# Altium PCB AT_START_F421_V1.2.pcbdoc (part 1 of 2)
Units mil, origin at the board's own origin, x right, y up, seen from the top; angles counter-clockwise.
Board outline 4706.37 x 3915.64 mil, 2 copper layers (Top Layer, Bottom Layer); 115 components, 101 nets, 469 pads, 319 vias.
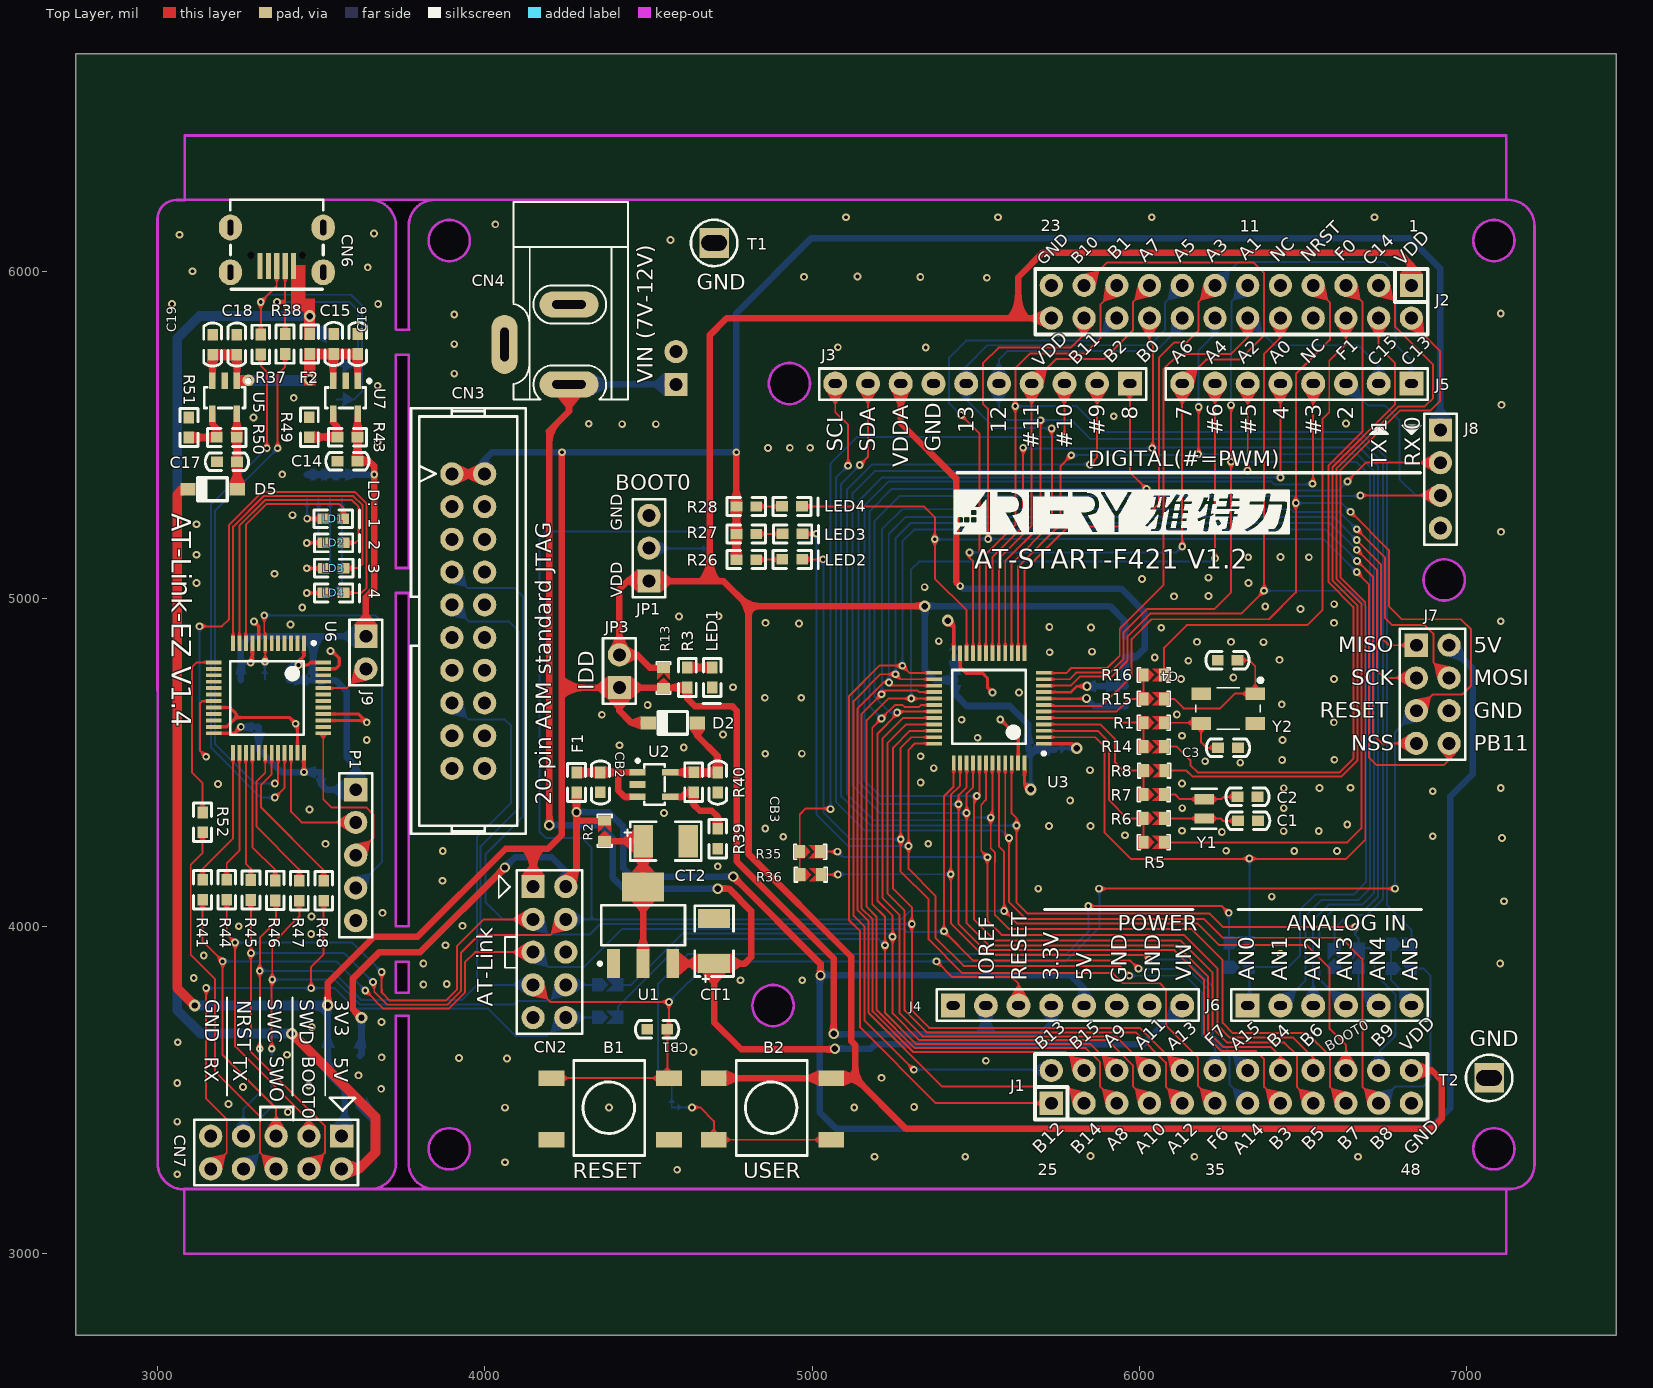
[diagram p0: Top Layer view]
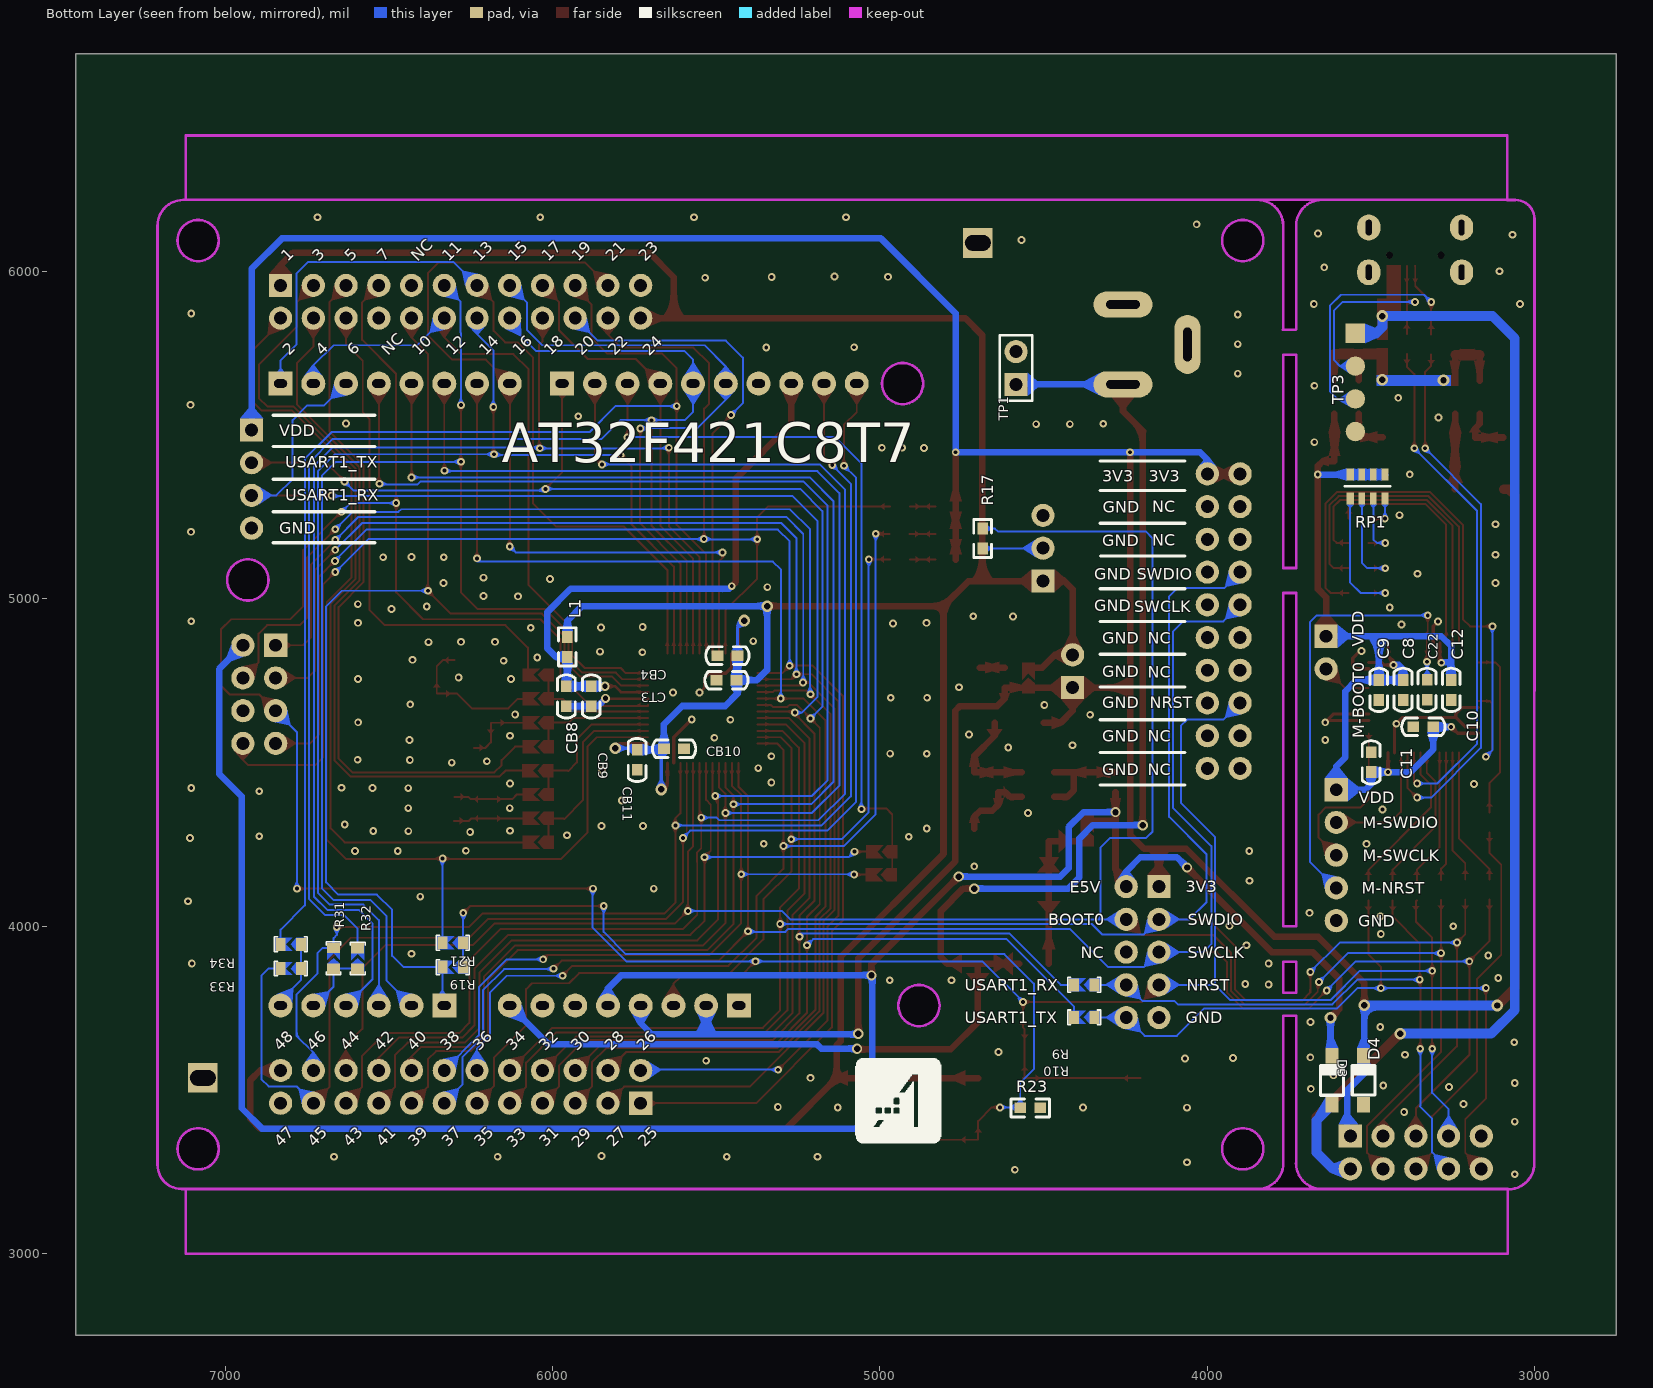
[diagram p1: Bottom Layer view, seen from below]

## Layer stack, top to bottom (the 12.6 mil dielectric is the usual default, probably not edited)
Top Layer: signal copper (thickness not stored)
Dielectric: dielectric 12.6, FR-4, Dk 4.8
Bottom Layer: signal copper (thickness not stored)

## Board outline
7456.37,2750 2750,2750 2750,6665.64 7456.37,6665.64
cut-out: 3727.81,3891.14 3766.62,3891.14 3767.37,3890.39 3767.37,3798.39 3766.52,3797.54 3727.68,3797.54
cut-out: 3728.37,4001.39 3767.37,4001.39 3767.37,5017.39 3728.37,5017.39
cut-out: 3767.37,5095.39 3767.37,5745.39 3728.37,5745.39 3728.37,5095.39
cut-out: 3728.37,3725.33 3767.37,3725.33 3767.37,3275.59 ccw(c3845.39,3275.59) 3845.39,3197.57 3649.76,3197.57 3649.76,3197.67 3650.4,3197.67 ccw(c3650.4,3275.65) 3728.37,3275.65
cut-out: 3767.63,5823.39 3728.11,5823.39 3728.11,6140.05 ccw(c3649.37,6140.05) 3649.37,6218.79 3846.15,6218.79 ccw(c3846.37,6140.05) 3767.63,6140.05
cut-out: 3846.15,6218.79 3846.37,6218.79 ccw(c3846.37,6140.05)
cut-out: 6931.05,5121.15 ccw(c6931.75,5056.84) 6867.44,5056.84 ccw(c6928.36,5056.73) 6927.55,4995.82 ccw(c6929.3,5058.48) 6931.05,5121.15
cut-out: 4931.05,5721.15 ccw(c4931.75,5656.84) 4867.44,5656.84 ccw(c4928.36,5656.73) 4927.55,5595.82 ccw(c4929.3,5658.48) 4931.05,5721.15
cut-out: 4881.05,3821.15 ccw(c4881.75,3756.84) 4817.44,3756.84 ccw(c4878.36,3756.73) 4877.55,3695.82 ccw(c4879.3,3758.49) 4881.05,3821.15
cut-out: 3892.05,3383.31 ccw(c3892.75,3319.01) 3828.44,3319 ccw(c3889.36,3318.9) 3888.55,3257.99 ccw(c3890.3,3320.65) 3892.05,3383.31
cut-out: 3892.07,6158 ccw(c3892.77,6093.69) 3828.46,6093.69 ccw(c3889.37,6093.58) 3888.57,6032.67 ccw(c3890.31,6095.34) 3892.07,6158
cut-out: 7083.05,6158 ccw(c7083.75,6093.69) 7019.44,6093.69 ccw(c7080.36,6093.58) 7079.55,6032.67 ccw(c7081.3,6095.34) 7083.05,6158
cut-out: 7083.05,3383.31 ccw(c7083.75,3319.01) 7019.44,3319 ccw(c7080.36,3318.9) 7079.55,3257.99 ccw(c7081.3,3320.65) 7083.05,3383.31

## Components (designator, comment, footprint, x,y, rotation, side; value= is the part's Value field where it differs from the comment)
B1 "PB,BLACK,SMD_2P" KEY_SOP_6*6 4203.37,3535.9 r0 top
B2 "PB,Blue,SMD_2P" KEY_SOP_6*6 4699.37,3535.9 r0 top
C1 "10pF" C0603 6300.61,4322.3 r0 top
C2 "10pF" C0603 6298.81,4395.51 r0 top
C3 "22pF" C0603 6239.42,4545.01 r0 top
C4 "22pF" C0603 6299.46,4813.05 r180 top
C8 "4.7uF" C0603 3401.34,4691.19 r90 bottom
C9 "0.1uF" C0603 3475.34,4691.19 r90 bottom
C10 "0.1uF" C0603 3370.45,4609.04 r180 bottom
C11 "0.1uF" C0603 3499.33,4531.85 r270 bottom
C12 "0.1uF" C0603 3254.34,4691.19 r90 bottom
C14 "10uF" C0603 3611.13,5421.07 r180 top
C15 "10uF" C0603 3538.55,5748.04 r90 top
C16 "0.1uF" C0603 3611.75,5748.08 r90 top
C17 "10uF" C0603 3243.13,5419.15 r180 top
C18 "10uF" C0603 3242.55,5746.04 r90 top
C19 "0.1uF" C0603 3168.55,5746.04 r90 top
C22 "0.1uF" C0603 3328.55,4753.15 r270 bottom
CB1 "0.1uF" C0603 4557.29,3685.29 r180 top
CB2 "1uF" C0603 4352.99,4470.15 r270 top
CB3 "1uF" C0603 4711.17,4469.85 r270 top
CB4 "0.1uF" C0603 5434.41,4827.14 r0 bottom
CB8 "1uF" C0603 5957.46,4733.24 r270 bottom
CB9 "0.1uF" C0603 5881.8,4733.24 r270 bottom
CB10 "0.1uF" C0603 5659.33,4541.73 r180 bottom
CB11 "0.1uF" C0603 5741.58,4538.9 r270 bottom
CN2 "CON10" HDR2X5 4147.19,4121.2 r270 top
CN3 "J-TAG" JTAG_20 3949.37,4932.09 r270 top
CN4 "DC_JACK" DC10B 4087.08,6074.51 r270 top
CN6 "USB_micro B" USB_MIC_DIP 3364.47,6017.38 r90 top
CN7 "CON10" HDR2X5 3562.55,3359.15 r180 top
CT1 "10uF/25V" C3528 4700.37,3886.09 r90 top
CT2 "10uF/25V" C3528 4483.37,4260.09 r0 top
CT3 "4.7uF" C0603 5437.41,4752.14 r0 bottom
D2 "DFLS130L" SOD-123 4573.92,4621.29 r0 top
D3 "DFLS130L" SOD-123 3618.54,3529.2 r270 bottom
D4 "SMF3.3A" SOD-123 3522.07,3529.86 r270 bottom
D5 "DFLS130L" SOD-123 3168.13,5335.15 r0 top
F1 "SMD0603B025TF" r0603 4280.19,4408.93 r90 top
F2 "SMD0603B025TF" r0603 3464.55,5809.04 r270 top
J1 "Header 12X2" HEAD2*12 5730.37,3459.51 r0 top
J2 "Header 12X2" HEAD2*12 6830.37,5957.66 r180 top
J3 "CON10" "HDR1X10 - 2#" 5970.37,5657.94 r180 top
J4 "CON8" "HDR1X8 - 2#" 5430.37,3757.94 r0 top
J5 "CON8" "HDR1X8 - 2#" 6830.37,5657.94 r180 top
J6 "CON6" "HDR1X6 -2#" 6330.37,3757.94 r0 top
J7 "Header 4X2" HDR2X4 6845.37,4858.51 r270 top
J8 "Header 4" HDR1X4 6918.97,5516.09 r270 top
J9 "1X2P_2.54M" HDR1X2 3636.55,4886.15 r270 top
JP1 "1X3P_2.54M" HDR1X3 4501.37,5055.09 r90 top
JP3 "1X2P_2.54M" HDR1X2 4410.97,4729.24 r90 top
L1 "BEAD" r0603 5954.58,4883.9 r270 bottom
LD1 "RED" LED0603 3506.59,5244.94 r0 top
LD2 "GREEN" LED0603 3507.55,5170.85 r0 top
LD3 "BLUE" LED0603 3507.59,5093.94 r0 top
LD4 "YELLOW" LED0603 3507.55,5017.94 r0 top
LED1 "RED" LED0603 4694.18,4790.28 r270 top
LED2 "RED" LED0603 4908.46,5120.29 r0 top
LED3 "YELLOW" LED0603 4909.61,5198.29 r0 top
LED4 "GREEN" LED0603 4907.61,5282.29 r0 top
P1 "Header 5" HDR1X5 3605.55,4417.15 r270 top
R1 "0R" SB-PAD 6043.39,4621.71 r0 top
R2 "0R" SB-PAD 4365.8,4291.56 r90 top
R3 "1K" r0603 4618.97,4729.31 r90 top
R5 "NC" SB-PAD 6043.43,4256.51 r0 top
R6 "0R" SB-PAD 6043.43,4329.51 r0 top
R7 "0R" SB-PAD 6043.43,4402.51 r0 top
R8 "NC" SB-PAD 6044.43,4475.58 r0 top
R9 "0R" SB-PAD 4375.64,3821.2 r0 bottom
R10 "0R" SB-PAD 4375.64,3721.65 r0 bottom
R13 "0R" SB-PAD 4545.77,4758.51 r90 top
R14 "NC" SB-PAD 6043.39,4548.71 r0 top
R15 "0R" SB-PAD 6043.39,4694.71 r0 top
R16 "NC" SB-PAD 6043.39,4767.71 r0 top
R17 "10K" r0603 4685.68,5154.09 r90 bottom
R19 "0R" SB-PAD 6304.41,3875.14 r0 bottom
R21 "NC" SB-PAD 6304.37,3949.94 r0 bottom
R23 "100K" r0603 4509.97,3445.29 r0 bottom
R26 "1K" r0603 4768.37,5120.09 r0 top
R27 "1K" r0603 4768.37,5198.09 r0 top
R28 "1K" r0603 4768.37,5282.09 r0 top
R31 "NC" SB-PAD 6668.58,3902.09 r90 bottom
R32 "0R" SB-PAD 6594.87,3901.66 r90 bottom
R33 "NC" SB-PAD 6798.97,3871 r0 bottom
R34 "0R" SB-PAD 6798.97,3945 r0 bottom
R35 "NC" SB-PAD 4993.37,4227.94 r0 top
R36 "0R" SB-PAD 4995.37,4157.94 r0 top
R37 "22R" r0603 3315.34,5808 r270 top
R38 "22R" r0603 3389.34,5808.96 r270 top
R39 "15K" r0603 4711.58,4237.13 r90 top
R40 "51K" r0603 4637.79,4409.45 r90 top
R41 "33R" r0603 3137.75,4081.19 r90 top
R43 "47K" r0603 3550.17,5493.87 r0 top
R44 "33R" r0603 3211.75,4081.19 r90 top
R45 "33R" r0603 3285.75,4080.19 r90 top
R46 "33R" r0603 3359.75,4079.19 r90 top
R47 "33R" r0603 3433.75,4078.19 r90 top
R48 "33R" r0603 3507.75,4078.19 r90 top
R49 "15K" r0603 3463.92,5555.03 r270 top
R50 "51K" r0603 3181.17,5492.94 r0 top
R51 "15K" r0603 3095.92,5554.11 r270 top
R52 "33R" r0603 3137.75,4286.98 r90 top
RP1 "1KΩ" RP_4-0603 3562.93,5307.03 r90 bottom
T1 "Test point" TestPoint 4700.37,6087.41 r0 top
T2 "Test point" TestPoint 7067.77,3536.94 r0 top
TP1 "1X2P_2.54M" HDR1X2 4583.83,5655.42 r90 bottom
TP3 "1X4P_2.54F" "HDR1X4 - top" 3547.13,5811.15 r270 bottom
U1 "AMS1117-5.0" SOT223 4483.37,4003.09 r90 top
U2 "RT9080N-08GJ5" SOT-23-5 4531.4,4370.15 r0 top
U3 "AT32F421C8T7" LQFP48 5540.46,4666.06 r90 top
U5 "RT9080N-08GJ5" SOT-23-5 3142.34,5601.04 r270 top
U6 "AT32F403ACCT7" "LQFP48 - 2" 3447.29,4865.15 r270 top
U7 "RT9080N-08GJ5" SOT-23-5 3511.55,5600.96 r270 top
Y1 "32.768KHz" "XTAL_SOP - FC-12M" 6197.85,4388.3 r270 top
Y2 "8MHZ" SMD_5032_4P 6270.61,4665.17 r180 top

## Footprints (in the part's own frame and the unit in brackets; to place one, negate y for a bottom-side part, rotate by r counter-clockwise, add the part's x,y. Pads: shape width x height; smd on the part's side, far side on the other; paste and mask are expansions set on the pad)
C0603 [mil]
  rect 36x32 smd mask+2: 1(-0.04,0.2) 2(60.96,0.2)
  silkscreen extent -35,-27 97,27
C3528 [mm]
  rect 1.5x2.5 smd mask+0.051: 1(0,0) 2(3.5,0)
  silkscreen extent -1.45,-1.5 4.5,1.5
DC10B [mil]
  oval 80x180 hole 25.59 slot 102.36 at 90 deg mask+2: 1(419.09,170) 2(175,170)
  oval 180x80 hole 25.59 slot 102.36 at 0 deg mask+2: 3(297.05,-26.85)
  silkscreen extent -138,0 465,350
HDR1X2 [mm]
  rect 1.8x1.8 hole 1 mask+0.051: 1(0,0)
  round 1.8 hole 1 mask+0.051: 2(2.54,0)
  silkscreen extent -1.27,-1.27 3.81,1.27
HDR1X3 [mm]
  rect 1.8x1.8 hole 1 mask+0.051: 1(0,0)
  round 1.8 hole 1 mask+0.051: 2(2.54,0) 3(5.08,0)
  silkscreen extent -1.27,-1.27 6.35,1.27
HDR1X4 [mm]
  rect 1.8x1.8 hole 1 mask+0.051: 1(0,0)
  round 1.8 hole 1 mask+0.051: 2(2.54,0) 3(5.08,0) 4(7.62,0)
  silkscreen extent -1.27,-1.27 8.89,1.27
"HDR1X4 - top" [mm]
  rect 1.5x1.5 smd mask+0.051: 1(0,0)
  round 1.5 smd mask+0.051: 2(2.54,0) 3(5.08,0) 4(7.62,0)
HDR1X5 [mm]
  rect 1.8x1.8 hole 1 mask+0.051: 1(0,0)
  round 1.8 hole 1 mask+0.051: 2(2.54,0) 3(5.08,0) 4(7.62,0) 5(10.16,0)
  silkscreen extent -1.27,-1.27 11.43,1.27
"HDR1X6 -2#" [mm]
  rect 1.86x1.86 hole 0.65 slot 1 at 0 deg mask+0.051: 1(0,0)
  round 1.86 hole 0.65 slot 1 at 0 deg mask+0.051: 2(2.54,0) 3(5.08,0) 4(7.62,0) 5(10.16,0) 6(12.7,0)
  silkscreen extent -1.27,-1.17 13.97,1.27
"HDR1X8 - 2#" [mm]
  rect 1.86x1.86 hole 0.65 slot 1 at 0 deg mask+0.051: 1(0,0)
  round 1.86 hole 0.65 slot 1 at 0 deg mask+0.051: 2(2.54,0) 3(5.08,0) 4(7.62,0) 5(10.16,0) 6(12.7,0) 7(15.24,0) 8(17.78,0)
  silkscreen extent -1.27,-1.17 19.05,1.27
"HDR1X10 - 2#" [mm]
  rect 1.86x1.86 hole 0.65 slot 1 at 0 deg mask+0.051: 1(0,0)
  round 1.86 hole 0.65 slot 1 at 0 deg mask+0.051: 2(2.54,0) 3(5.08,0) 4(7.62,0) 5(10.16,0) 6(12.7,0) 7(15.24,0) 8(17.78,0) 9(20.32,0) 10(22.86,0)
  silkscreen extent -1.27,-1.17 24.1,1.27
HDR2X4 [mm]
  rect 1.8x1.8 hole 1 mask+0.051: 1(0,0)
  round 1.8 hole 1 mask+0.051: 2(0,2.54) 3(2.54,0) 4(2.54,2.54) 5(5.08,0) 6(5.08,2.54) 7(7.62,0) 8(7.62,2.54)
  silkscreen extent -1.27,-1.27 8.89,3.81
HDR2X5 [mm]
  rect 1.8x1.8 hole 1 mask+0.051: 1(0,0)
  round 1.8 hole 1 mask+0.051: 2(0,2.54) 3(2.54,0) 4(2.54,2.54) 5(5.08,0) 6(5.08,2.54) 7(7.62,0) 8(7.62,2.54) 9(10.16,0) 10(10.16,2.54)
  silkscreen extent -1.27,-1.27 11.43,3.81
HEAD2*12 [mm]
  rect 1.8x1.8 hole 1 mask+0.051: 1(0,0)
  round 1.8 hole 1 mask+0.051: 2(0,2.54) 3(2.54,0) 4(2.54,2.54) 5(5.08,0) 6(5.08,2.54) 7(7.62,0) 8(7.62,2.54) 9(10.16,0) 10(10.16,2.54) 11(12.7,0) 12(12.7,2.54) 13(15.24,0) 14(15.24,2.54) 15(17.78,0) 16(17.78,2.54) 17(20.32,0) 18(20.32,2.54) 19(22.86,0) 20(22.86,2.54) 21(25.4,0) 22(25.4,2.54) 23(27.94,0) 24(27.94,2.54)
  silkscreen extent -1.27,-1.27 29.19,3.81
JTAG_20 [mm]
  round 1.8 hole 1 mask+0.051: 1(-11.43,-1.27) 2(-11.43,1.27) 3(-8.89,-1.27) 4(-8.89,1.27) 5(-6.35,-1.27) 6(-6.35,1.27) 7(-3.81,-1.27) 8(-3.81,1.27) 9(-1.27,-1.27) 10(-1.27,1.27) 11(1.27,-1.27) 12(1.27,1.27) 13(3.81,-1.27) 14(3.81,1.27) 15(6.35,-1.27) 16(6.35,1.27) 17(8.89,-1.27) 18(8.89,1.27) 19(11.43,-1.27) 20(11.43,1.27)
  silkscreen extent -16.51,-4.45 16.51,4.45
KEY_SOP_6*6 [mm]
  rect 2x1.2 smd mask+0.051: 1(0,0) 1(9.119,0) 2(0,-4.775) 2(9.119,-4.775)
  silkscreen extent 1.73,-5.99 7.24,1.4
LED0603 [mil]
  rect 36x32 smd mask+2: 1(-0.04,0.2) 2(60.96,0.2)
  silkscreen extent -28,-28 110,27
LQFP48 [mm]
  rect 0.3x1.2 smd mask+0.051: 1(-2.75,-4.25) 2(-2.25,-4.25) 3(-1.75,-4.25) 4(-1.25,-4.25) 5(-0.75,-4.25) 6(-0.25,-4.25) 7(0.25,-4.25) 8(0.75,-4.25) 9(1.25,-4.25) 10(1.75,-4.25) 11(2.25,-4.25) 12(2.75,-4.25) 25(2.75,4.25) 26(2.25,4.25) 27(1.75,4.25) 28(1.25,4.25) 29(0.75,4.25) 30(0.25,4.25) 31(-0.25,4.25) 32(-0.75,4.25) 33(-1.25,4.25) 34(-1.75,4.25) 35(-2.25,4.25) 36(-2.75,4.25)
  rect 1.2x0.3 smd mask+0.051: 13(4.25,-2.75) 14(4.25,-2.25) 15(4.25,-1.75) 16(4.25,-1.25) 17(4.25,-0.75) 18(4.25,-0.25) 19(4.25,0.25) 20(4.25,0.75) 21(4.25,1.25) 22(4.25,1.75) 23(4.25,2.25) 24(4.25,2.75) 37(-4.25,2.75) 38(-4.25,2.25) 39(-4.25,1.75) 40(-4.25,1.25) 41(-4.25,0.75) 42(-4.25,0.25) 43(-4.25,-0.25) 44(-4.25,-0.75) 45(-4.25,-1.25) 46(-4.25,-1.75) 47(-4.25,-2.25) 48(-4.25,-2.75)
  silkscreen extent -3.64,-4.37 2.96,2.86
"LQFP48 - 2" [mm]
  rect 1.2x0.3 smd mask+0.051: 1(0,0) 2(0,-0.5) 3(0,-1) 4(0,-1.5) 5(0,-2) 6(0,-2.5) 7(0,-3) 8(0,-3.5) 9(0,-4) 10(0,-4.5) 11(0,-5) 12(0,-5.5) 25(8.5,-5.5) 26(8.5,-5) 27(8.5,-4.5) 28(8.5,-4) 29(8.5,-3.5) 30(8.5,-3) 31(8.5,-2.5) 32(8.5,-2) 33(8.5,-1.5) 34(8.5,-1) 35(8.5,-0.5) 36(8.5,0)
  rect 0.3x1.2 smd mask+0.051: 13(1.5,-7) 14(2,-7) 15(2.5,-7) 16(3,-7) 17(3.5,-7) 18(4,-7) 19(4.5,-7) 20(5,-7) 21(5.5,-7) 22(6,-7) 23(6.5,-7) 24(7,-7) 37(7,1.5) 38(6.5,1.5) 39(6,1.5) 40(5.5,1.5) 41(5,1.5) 42(4.5,1.5) 43(4,1.5) 44(3.5,1.5) 45(3,1.5) 46(2.5,1.5) 47(2,1.5) 48(1.5,1.5)
  silkscreen extent -0.12,-5.71 7.11,0.89
r0603 [mil]
  rect 36x32 smd mask+2: 1(-0.04,0.2) 2(60.96,0.2)
  silkscreen extent -28,-27 89,27
RP_4-0603 [mm]
  rect 0.95x0.55 smd mask+0.051: 1(0,-2.7) 4(0,0) 5(1.85,0) 8(1.85,-2.7)
  rect 0.95x0.5 smd mask+0.051: 2(0,-1.8) 3(0,-0.9) 6(1.85,-0.9) 7(1.85,-1.8)
  silkscreen extent 0.94,-3.1 0.94,0.43
SB-PAD [mm]
  rect 0.8x1 smd paste+0.102 mask+0.102: 1(-0.799,0.003) 2(0.799,0.002)
  Top Layer region: -1.2,-0.5 -1.2,0.5 -0.418,0.5 0.025,0 -0.433,-0.5
  Top Layer region: -0.119,0.5 0.381,0 -0.119,-0.5 1.2,-0.5 1.2,0.5
  silkscreen extent -1.28,-0.58 1.28,0.58
SMD_5032_4P [mm]
  rect 1.5x1 smd mask+0.051: 1(-2.1,-1.15) 2(2.1,-1.15) 3(2.1,1.15) 4(-2.1,1.15)
  silkscreen extent -2.65,-2.35 2.5,1.6
SOD-123 [mm]
  rect 1.2x1 smd mask+0.051: 1(1.905,0) 2(-1.905,0)
  silkscreen extent -1.14,-0.89 1.14,0.89
SOT223 [mm]
  rect 2.25x1 smd mask+0.051: 1(-2.975,2.3) 2(-2.975,0) 3(-2.975,-2.3)
  rect 2.25x3.25 smd mask+0.051: 4(2.975,0)
  silkscreen extent -3.1,-3.25 1.55,3.47
SOT-23-5 [mil]
  rect 50x20 smd mask+2: 1(-65,100) 2(-65,63) 3(-65,25) 4(35,25) 5(35,100)
  silkscreen extent -65,1 18,135
TestPoint [mm]
  rect 2.3x2.3 hole 1.2 slot 2 at 0 deg mask+0.051: 1(0,0)
  silkscreen extent -1.8,-1.8 1.8,1.8
USB_MIC_DIP [mm]
  rect 2x0.4 smd mask+0.051: 1(0,-1.3) 2(0,-0.65) 3(0,0) 4(0,0.65) 5(0,1.3)
  oval 2x1.8 hole 0.45 slot 1.2 at 0 deg mask+0.051: 6(-0.495,-3.6) 7(2.975,-3.6) 8(2.975,3.6) 9(-0.495,3.6)
  round 0.5 hole 0.55 unplated mask+0.051: MH1(0.825,2) MH2(0.825,-2)
  silkscreen extent -1.82,-3.6 5.12,3.6
"XTAL_SOP - FC-12M" [mm]
  rect 0.8x1.5 smd mask+0.051: 1(0,0) 2(1.5,0)
  silkscreen extent -0.81,-0.99 2.29,0.94

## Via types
v1: diameter 23.62, hole 11.81, Top Layer to Bottom Layer, 298 vias
v2: diameter 35.43, hole 19.68, Top Layer to Bottom Layer, 11 vias
v3: diameter 31.5, hole 19.68, Top Layer to Bottom Layer, 8 vias
v4: diameter 27.56, hole 15.75, Top Layer to Bottom Layer, 2 vias

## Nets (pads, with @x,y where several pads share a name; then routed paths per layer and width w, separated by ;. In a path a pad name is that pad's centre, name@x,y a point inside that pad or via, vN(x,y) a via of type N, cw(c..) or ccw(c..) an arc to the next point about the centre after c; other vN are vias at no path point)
3V3: CN2.1 CN3.1 CN3.2 CN7.1 D2.2 D4.2 D5.2 J4.2 J4.4 J8.1 JP3.1 R3.1 R13.1 R26.1 R27.1 R28.1 | length 11849
  Top Layer w20: v2(3520,3758.39) 3520,3826.85 3661.09,3967.94 3794.35,3967.94 4063.5,4237.09 4147.19,4237.09 ; CN3.1@3899.37,5382.09 CN3.2@3999.37,5382.09 ; CN2.1@4147.19,4121.2 4147.19,4237.09 ; v1(4235.37,5447.94) 4235.37,4729.31 ; JP3.1@4410.97,4729.24 4545.77,4729.2 R13.1@4545.97,4728.99 ; D2.2@4498.92,4621.29 4448.11,4621.29 4410.97,4658.44 JP3.1@4410.97,4729.24 4235.45,4729.24 4235.37,4729.31 ; R13.1@4545.77,4729.24 R3.1@4618.73,4729.24 ; R3.1@4618.77,4729.28 4618.77,4694.88 4641.13,4672.52 4755.36,4672.52 4769.37,4658.51 4769.37,4198.09 5065.37,3902.09 v3(5065.37,3672.09) ; R26.1@4768.33,5120.29 R27.1@4768.33,5198.29 R28.1@4768.33,5282.29 v1(4768.33,5448.13) ; 4147.19,4237.09 4192.56,4237.09 4235.37,4279.9 4235.37,4729.31
  Top Layer w30: D5.2@3093.13,5335.15 3077.28,5335.15 3060.07,5317.94 3060.07,3811.2 v2(3113.33,3757.94)
  Bottom Layer w20: v2(3520,3758.39) 3520,3606.93 D4.2@3522.07,3604.86 3522.07,3548.59 3572.65,3498.01 3572.65,3369.25 CN7.1@3562.55,3359.15 ; CN3.2@3999.37,5382.09 3999.37,5426.09 4021.41,5448.13 v1(4768.33,5448.13) 4768.33,5872.85 4996.57,6101.09 6826.37,6101.09 6918.97,6008.49 J8.1@6918.97,5516.09 ; v3(5065.37,3672.09) 5067.37,3670.09 5532.37,3670.09 ; J4.2@5530.37,3757.94 5530.37,3672.09 5532.37,3670.09 ; J4.4@5730.37,3757.94 5730.37,3704.09 5696.37,3670.09 5532.37,3670.09
  Bottom Layer w30: v2(3113.33,3757.94) v2@3519.55,3757.94
5V: CN2.2 D3.2 F1.1 J4.5 J7.2 R2.2 | length 7292.7
  Top Layer w6: 4279.99,4329.09 4286.05,4323.03
  Top Layer w20: v2(3623.16,3720.46) 3597.12,3746.51 3597.12,3840.57 3677.74,3921.2 3802.87,3921.2 v3(4061.26,4179.59) ; CN2.2@4247.19,4121.2 4247.19,4140.9 4279.99,4173.71 4279.99,4329.09 v3(4279.99,4349.02) F1.1@4279.99,4408.89 ; 4286.05,4323.03 R2.2@4365.72,4323.03 ; v3(4758.61,4151.85) 5025.37,3885.09 v3(5025.37,3849.94)
  Bottom Layer w20: D3.2@3618.54,3604.2 3623.16,3608.81 v2(3623.16,3720.46) ; v3(4061.26,4179.59) 4092.36,4210.7 4204.06,4210.7 4247.19,4167.57 CN2.2@4247.19,4121.2 ; v3(4279.99,4349.02) 4377.18,4349.02 4423.14,4303.06 4423.14,4177.32 4448.61,4151.85 v3(4758.61,4151.85) ; J4.5@5830.37,3757.94 5830.37,3809.94 5789.37,3850.94 5026.37,3850.94 v3(5025.37,3849.94) 5022.37,3846.94 5022.37,3432.09 5072.37,3382.09 6887.37,3382.09 6949.3,3444.01 6949.3,4396.67 7018.37,4465.74 7018.37,4785.51 J7.2@6945.37,4858.51
$1N792: LD1.1 RP1.1 | length 111.5
  Top Layer w6: v1(3457.07,5245.15) LD1.1@3506.55,5245.15
  Bottom Layer w6: RP1.1@3456.63,5307.03 3456.63,5245.58 v1(3457.07,5245.15)
$1N793: LD2.1 RP1.2 | length 217.4
  Top Layer w6: v1(3456.07,5171.05) LD2.1@3507.51,5171.05
  Bottom Layer w6: v1(3456.07,5171.05) 3481.74,5171.05 3492.07,5181.38 RP1.2@3492.07,5307.03
$1N794: LD3.1 RP1.3 | length 326.6
  Top Layer w6: v1(3456.07,5093.86) 3507.26,5093.86 LD3.1@3507.55,5094.15
  Bottom Layer w6: v1(3456.07,5093.86) 3511.07,5093.86 3527.5,5110.29 RP1.3@3527.5,5307.03
$1N795: LD4.1 RP1.4 | length 428.7
  Top Layer w6: v1(3456.07,5018.15) LD4.1@3507.51,5018.15
  Bottom Layer w6: v1(3456.07,5018.15) 3531.35,5018.15 3562.93,5049.73 RP1.4@3562.93,5307.03
$1N806: C15.1 C16.1 C18.1 C19.1 F2.2 U5.1 U5.3 U7.1 U7.3 | length 541.8
  Top Layer w20: U5.3@3167.34,5666.04 3167.34,5745 C19.1@3168.34,5746 ; U5.1@3242.34,5666.04 C18.1@3242.34,5746 ; U7.3@3536.55,5668.04 C15.1@3536.55,5746.2 ; U7.1@3611.55,5668.04 C16.1@3611.55,5748.04
  Top Layer w30: C19.1@3168.34,5746 C18.1@3242.34,5746 ; F2.2@3464.75,5748.08 3538.34,5748.08 C16.1@3611.51,5748.08 ; C15.1@3536.55,5746.2 C15.1@3538.34,5748
  other v2: 3278.07,5667.86 3465.55,5669.15
$1N944: R50.1 R51.2 U5.4 | length 163.6
  Top Layer w20: R51.2@3096.13,5493.15 R50.1@3181.13,5493.15 3181.13,5521.15 3167.34,5534.93 U5.4@3167.34,5566.04
$1N945: R43.1 R49.2 U7.4 | length 163.5
  Top Layer w20: R49.2@3464.13,5494.07 R43.1@3550.13,5494.07 3550.13,5525.07 3536.55,5538.65 U7.4@3536.55,5565.96
$2N438: C2.1 R7.2 Y1.1 | length 232.8
  Top Layer w6: R7.2@6074.9,4402.58 6108.93,4402.58 6123.21,4388.3 Y1.1@6197.85,4388.3 6249.85,4388.3 6257.06,4395.51 C2.1@6298.81,4395.51
$2N447: C1.1 R6.2 Y1.2 | length 228.3
  Top Layer w6: R6.2@6074.9,4329.58 6114.45,4329.58 ; 6114.78,4329.25 Y1.2@6197.85,4329.25 6247.91,4329.25 6254.85,4322.3 C1.1@6300.61,4322.3
$2N462: R7.1 R8.1 U3.4 | length 478.8
  Top Layer w6: U3.4@5707.79,4616.85 5879.21,4616.85 5925.05,4571.01 5925.05,4500.97 5951.85,4474.17 5953.37,4475.68 R8.1@6012.96,4475.68 ; R7.1@6011.96,4402.61 R8.1@6011.96,4475.51
$2N463: R1.1 R14.1 U3.5 | length 383.2
  Top Layer w6: U3.5@5707.79,4636.53 5934.73,4636.53 5949.45,4621.81 R1.1@6011.92,4621.81 R14.1@6011.92,4548.81
$2N464: R15.1 R16.1 U3.6 | length 393.1
  Top Layer w6: U3.6@5707.79,4656.22 5930.19,4656.22 5968.79,4694.81 R15.1@6011.92,4694.81 R16.1@6011.92,4767.81
$2N471: R5.1 R6.1 U3.3 | length 592.2
  Top Layer w6: U3.3@5707.79,4597.16 5871.57,4597.16 5906.68,4562.05 5906.68,4385.21 5964.27,4327.62 5966.26,4329.61 R6.1@6011.96,4329.61 ; R5.1@6011.44,4257.13 R6.1@6011.44,4329.09
$2N484: JP1.2 R17.1 | length 185.1
  Bottom Layer w6: JP1.2@4501.37,5155.09 ccw(c4502.37,5155.09) 4502.37,5154.09 R17.1@4685.88,5154.09
$2N487: C3.1 R1.2 Y2.3 | length 230.4
  Top Layer w6: R1.2@6074.86,4621.79 6186.04,4621.79 Y2.3@6187.93,4619.9 6187.93,4561.66 6204.37,4545.22 C3.1@6239.38,4545.22
$2N488: C4.1 R15.2 Y2.1 | length 454
  Top Layer w6: R15.2@6074.86,4694.79 6105.52,4694.79 6134.37,4665.94 6246.37,4665.94 6290.88,4710.45 Y2.1@6353.28,4710.45 6353.28,4794.03 6334.47,4812.85 C4.1@6299.5,4812.85
$3N526: LED1.1 R3.2 | length 75.4
  Top Layer w20: R3.2@4618.77,4790.28 LED1.1@4694.18,4790.28
$3N531: CB3.1 D2.1 R40.2 U2.5 | length 321.1
  Top Layer w6: R40.2@4637.33,4470.15 R40.2@4637.59,4470.41
  Top Layer w20: U2.5@4566.4,4470.15 R40.2@4637.33,4470.15 ; R40.2@4637.59,4470.41 4710.85,4470.41 4710.85,4520.42 4648.92,4582.35 D2.1@4648.92,4621.29
$3N595: B2.2 R19.1 R21.1 R23.2 | length 3021.5
  Top Layer w6: v1(4633.09,3446.74) 4657.58,3446.74 4699.37,3404.95 B2.2@4699.37,3347.9 B2.2@5058.37,3347.9 ; v1(5843.33,4061.94) 6251.52,4061.94 v1(6272.52,4040.94)
  Bottom Layer w6: R23.2@4570.93,3445.09 R23.2@4570.93,3446.74 ; v1(4633.09,3446.74) R23.2@4570.93,3446.74 ; v1@5843.37,4061.94 5843.37,3982.94 5775.37,3914.94 4619.24,3914.94 4529.37,3825.07 4529.37,3563.94 4570.93,3522.38 R23.2@4570.93,3446.74 ; v1(6272.52,4040.94) v1@6272.95,4040.94 ; R21.1@6272.91,3949.84 v1@6272.91,4040.9 ; R19.1@6272.95,3875.04 R21.1@6272.91,3949.84
$3N598: LED3.1 R27.2 | length 80.3
  Top Layer w6: R27.2@4829.33,5198.29 LED3.1@4909.61,5198.29
$3N599: LED4.1 R28.2 | length 78.3
  Top Layer w6: R28.2@4829.33,5282.29 LED4.1@4907.61,5282.29
$3N606: LED2.1 R26.2 | length 79.1
  Top Layer w6: R26.2@4829.33,5120.29 LED2.1@4908.46,5120.29
$3N618: R39.2 R40.1 U2.4 | length 240.7
  Top Layer w20: U2.4@4566.4,4395.15 4601.92,4395.15 4616.19,4409.41 R40.1@4637.59,4409.41 4637.59,4371.87 4656.37,4353.09 4693.37,4353.09 4711.37,4335.08 R39.2@4711.37,4298.09
$3N621: CT2.1 R2.1 U1.2 U1.4 | length 491.8
  Top Layer w20: R2.1@4365.69,4260.09 CT2.1@4483.37,4260.09 U1.4@4483.37,4120.21 U1.2@4483.37,3885.96
$3N625: CB2.1 F1.2 U2.1 U2.3 | length 306.8
  Top Layer w6: F1.2@4279.99,4469.89 F1.2@4280.29,4470.19
  Top Layer w20: F1.2@4280.29,4470.19 CB2.1@4353.19,4470.19 U2.1@4466.4,4470.15 ; 4407.4,4468.19 4407.4,4415.15 4427.4,4395.15 U2.3@4466.4,4395.15
A0: J2.10 J6.1 R19.2 U3.10 | length 3527
  Top Layer w6: U3.10@5707.79,4734.96 5789.39,4734.96 5817.37,4762.94 5914.37,4762.94 5963.37,4811.94 5963.37,4885.94 6032.37,4954.94 6310.37,4954.94 v1(6380.37,5024.94) 6380.37,5748.94 6429.95,5798.52 J2.10@6429.95,5857.24
  Bottom Layer w6: J6.1@6330.37,3757.94 6335.88,3763.45 R19.2@6335.88,3875.07 6454.7,3875.07 6489.37,3909.74 6489.37,4049.94 6536.37,4096.94 6654.37,4096.94 6691.37,4133.94 6691.37,4976.94 6643.37,5024.94 v1(6380.37,5024.94)
A1: J2.11 J6.2 U3.11 | length 3928.1
  Top Layer w6: U3.11@5707.79,4754.64 5786.08,4754.64 5806.37,4774.94 5909.16,4774.94 5951.37,4817.15 5951.37,4897.94 6022.37,4968.94 6228.37,4968.94 6279.37,5019.94 v1(6279.37,5418.94) v1(6279.37,5591.94)
  Bottom Layer w6: v1(6279.37,5418.94) 6662.37,5418.94 6704.37,5376.94 6704.37,4115.94 6669.37,4080.94 6556.37,4080.94 6507.37,4031.94 6507.37,3834.94 J6.2@6430.37,3757.94 ; v1(6279.37,5591.94) 6279.37,5812.94 6281.37,5814.94 6281.37,5908.66 J2.11@6329.95,5957.24
A2: J2.14 J6.3 U3.14 | length 3826.2
  Top Layer w6: U3.14@5629.05,4833.38 5629.05,5098.61 5758.37,5227.94 5758.37,5405.94 v1(5791.37,5438.94) ; v1@6180.37,5441.94 v1(6180.37,5585.94)
  Bottom Layer w6: v1(5791.37,5438.94) 6015.98,5438.94 6016.37,5439.34 6175.77,5439.34 v1(6178.37,5441.94) 6664.37,5441.94 6716.37,5389.94 6716.37,4101.94 6680.52,4066.09 6577.52,4066.09 6530.37,4018.94 J6.3@6530.37,3757.94 ; v1@6181.37,5585.94 6180.37,5586.94 6180.37,5758.94 6229.95,5808.52 J2.14@6229.95,5857.24
A3: J2.18 J6.4 U3.18 | length 3988.6
  Top Layer w6: U3.18@5550.31,4833.38 5550.31,5127.87 5644.37,5221.94 v1(5644.37,5461.94) ; J2.18@6029.95,5857.24 6029.95,5787.36 6040.37,5776.94 v1@6040.37,5460.15
  Bottom Layer w6: v1(5644.37,5461.94) 5646.16,5460.15 v1(6038.37,5460.15) ; v1@6038.37,5462.75 6671.56,5462.75 6728.37,5405.94 6728.37,4090.94 6687.37,4049.94 6592.22,4049.94 6549.37,4007.09 6549.37,3838.94 J6.4@6630.37,3757.94
A4: J6.5 R31.1 R32.1 | length 215
  Bottom Layer w6: R32.1@6594.98,3870.2 6595.4,3870.62 R31.1@6668.68,3870.62 6668.68,3814.78 6725.52,3757.94 J6.5@6730.37,3757.94
A5: J6.6 R33.1 R34.1 | length 213
  Bottom Layer w6: R34.1@6767.5,3944.89 R33.1@6767.5,3870.89 6767.5,3836.81 6830.37,3773.94 J6.6@6830.37,3757.94
ATLINK_5V: CN6.1 CN7.2 D3.1 F2.1 TP3.1 | length 3869.9
  Top Layer w30: v2(3410.68,3672.02) 3665.54,3417.16 3665.54,3308.83 3615.85,3259.15 CN7.2@3562.55,3259.15
  Bottom Layer w30: v2(3410.68,3672.02) 3132.07,3672.02 3060.07,3744.02 3060.07,5795.67 3128.55,5864.15 v2(3464.75,5864.15) 3464.75,5830.52 3484.13,5811.15 TP3.1@3547.13,5811.15 ; CN7.2@3562.55,3259.15 3615.85,3259.15 3665.54,3308.83 3665.54,3407.2 D3.1@3618.54,3454.2
ATLK_BOOT0: R45.2 U6.27 | length 395.7
  Top Layer w6: U6.27@3270.12,4530.5 3270.12,4191.27 3285.55,4175.85 R45.2@3285.55,4141.15
ATLK_NRST: R46.2 U6.28 | length 419.2
  Top Layer w6: U6.28@3289.81,4530.5 3289.81,4242.01 3359.55,4172.27 R46.2@3359.55,4140.15
ATLK_RX: CN2.10 CN7.10 R10.1 R48.1 | length 2160.8
  Top Layer w6: v1(3148.58,3811.2) 3148.58,3473.83 3211.55,3410.86 3211.55,3308.15 CN7.10@3162.55,3259.15 ; v1(3469.37,3810.94) 3469.37,3875.94 3507.55,3914.11 R48.1@3507.55,4078.15
  Bottom Layer w6: v1(3148.58,3811.2) 3148.84,3810.94 v1(3469.37,3810.94) 3541.31,3810.94 3603.1,3749.15 4008.58,3749.15 4092.63,3665.09 4191.08,3665.09 CN2.10@4247.19,3721.2 ; CN2.10@4247.19,3721.55 R10.1@4344.17,3721.55
ATLK_SWCLK: R41.2 U6.25 | length 427
  Top Layer w6: R41.2@3137.55,4142.15 3137.55,4175.11 3230.75,4268.32 U6.25@3230.75,4530.5
ATLK_SWDIO: R44.2 U6.26 | length 404.5
  Top Layer w6: R44.2@3211.55,4142.15 3211.55,4192.42 3250.44,4231.31 U6.26@3250.44,4530.5
ATLK_SWO: R52.2 U6.13 | length 528.8
  Top Layer w6: R52.2@3137.58,4347.94 3137.58,4437.46 3106.07,4468.97 3106.07,4792.31 3119.84,4806.09 U6.13@3171.7,4806.09
ATLK_TX: CN2.8 CN7.8 R9.1 R47.1 | length 1941.2
  Top Layer w6: v1(3348.86,3626.09) 3348.86,3831.19 3350.58,3832.91 v1(3350.58,3836.94) 3350.58,3947.06 3433.55,4030.03 R47.1@3433.55,4078.15
  Bottom Layer w6: CN7.8@3262.55,3259.15 3312.55,3309.15 3312.55,3412.15 3350.58,3450.18 3348.86,3451.9 v1(3348.86,3626.09) ; v1(3350.58,3836.94) 3541.37,3836.94 3617.16,3761.15 4089.43,3761.15 4099.37,3771.09 4197.08,3771.09 CN2.8@4247.19,3821.2 4247.29,3821.1 R9.1@4344.17,3821.1
BOOT0: CN2.4 CN7.4 J1.20 R17.2 R45.1 U3.44 | length 7187.3
  Top Layer w6: R45.1@3285.55,4080.15 v1(3285.55,3917.94) 3285.55,3616.09 3511.53,3390.11 3511.53,3308.13 CN7.4@3462.55,3259.15 ; v1@3654.37,3833.94 v1(3658.22,3830.09) 3662.07,3826.24 3662.07,3800.24 3701.97,3760.34 3884.89,3760.34 3927.18,3802.63 3927.18,3919.9 3980.53,3973.25 4199.23,3973.25 CN2.4@4247.19,4021.2 ; U3.44@5569.99,4498.74 5569.99,4244.42 5586.37,4228.04 v1@5586.37,4047.94 ; v1(5586.37,4046.94) v1@5586.37,4047.94 ; J1.20@6630.8,3559.94 6630.8,3636.51 6580.37,3686.94 6580.37,3871.94 6509.37,3942.94 6242.37,3942.94 6176.37,4008.94 5625.37,4008.94 v1@5586.37,4047.94
  Bottom Layer w6: v1(3285.55,3917.94) 3570.37,3917.94 v1@3654.37,3833.94 ; CN2.4@4247.19,4021.2 4325.97,4021.2 ; R17.2@4685.88,5215.05 4648.56,5215.05 4639.6,5206.09 4187.37,5206.09 4166.94,5185.65 4166.94,4289.38 4186.37,4269.94 4295.37,4269.94 4325.97,4239.34 4325.97,4021.2 ; v1(5586.37,4046.94) 5299.11,4046.94 5273.37,4021.2 4325.97,4021.2
D0: J2.13 J5.1 U3.13 | length 2461.2
  Top Layer w6: U3.13@5648.73,4833.38 5648.73,5088.3 5781.37,5220.94 5988.37,5220.94 6059.37,5291.94 6059.37,5737.94 6105.37,5783.94 6144.37,5783.94 6179.37,5818.94 6179.37,5906.66 J2.13@6229.95,5957.24
  Bottom Layer w6: J2.13@6229.95,5957.24 6301.65,6028.94 6747.37,6028.94 6782.37,5993.94 6782.37,5777.09 6830.37,5729.09 J5.1@6830.37,5657.94
D1: J2.12 J5.2 U3.12 | length 2055.1
  Top Layer w6: U3.12@5707.79,4774.33 5707.79,4773.52 5776.37,4773.52 5791.79,4788.94 5901.37,4788.94 5939.37,4826.94 5939.37,4908.94 6072.37,5041.94 6072.37,5701 6119.37,5748 6278.43,5748 6329.95,5799.52 J2.12@6329.95,5857.24
  Bottom Layer w6: J2.12@6329.95,5857.24 6412.25,5774.94 6668.55,5774.94 6730.37,5713.12 J5.2@6730.37,5657.94
D2: J1.7 J5.3 J8.3 R9.2 U3.31 | length 5833.2
  Top Layer w6: v1@5261.87,4650.44 5199.37,4587.94 5199.37,4077.94 5245.37,4031.94 v1(5245.37,3967.94) 5245.37,3733.94 5327.37,3651.94 5902.37,3651.94 5980.37,3573.94 5980.37,3510.36 J1.7@6030.8,3459.94 ; v1@5267.65,4656.22 U3.31@5373.14,4656.22 ; v1@6674.37,5316.09 J8.3@6918.97,5316.09
  Bottom Layer w6: R9.2@4407.11,3821.12 4447.56,3821.12 4604.51,3978.08 5235.23,3978.08 v1(5245.37,3967.94) ; v1(5259.37,4652.94) 5237.94,4652.94 5190.56,4700.32 5190.56,5238.13 5266.37,5313.94 6672.37,5313.94 v1(6674.37,5315.94) ; J5.3@6630.37,5657.94 6697.37,5590.94 6748.52,5590.94 6793.37,5546.09 6793.37,5365.94 6843.22,5316.09 J8.3@6918.97,5316.09
D3: J1.17 J5.4 U3.41 | length 4821.7
  Top Layer w6: U3.41@5510.94,4498.74 5510.94,4406.3 v1(5502.57,4397.94) 5494.37,4389.74 5494.37,4019.94 5557.37,3956.94 6123.8,3956.94 6223.37,3857.37 6223.37,3688.94 6267.37,3644.94 6442.25,3644.94 6481.37,3605.82 6481.37,3508.51 J1.17@6530.37,3459.51 ; v1@6530.37,5351.94 J5.4@6530.37,5657.94
  Bottom Layer w6: v1(5502.57,4397.94) 5207.37,4397.94 5159.37,4445.94 5159.37,5284.94 5233.56,5359.13 6402.75,5359.13 6411.75,5350.13 6526.56,5350.13 v1(6528.37,5351.94)
D4: J1.15 J5.5 U3.39 | length 4655.4
  Top Layer w6: U3.39@5471.57,4498.74 5471.57,4425.13 5447.07,4400.64 v1(5447.07,4372.94) 5447.07,4006.24 5526.37,3926.94 6106.37,3926.94 6196.37,3836.94 6196.37,3672.5 6249.94,3618.94 6355.37,3618.94 6380.37,3593.94 6380.37,3509.51 J1.15@6430.37,3459.51 ; v1(6430.37,5370.94) J5.5@6430.37,5657.94
  Bottom Layer w6: v1(5447.07,4372.94) 5209.37,4372.94 5141.37,4440.94 5141.37,5297.94 5214.56,5371.13 6430.18,5371.13 v1(6430.37,5370.94)
D5: J1.16 J5.6 U3.40 | length 4543.5
  Top Layer w6: U3.40@5491.25,4498.74 5491.25,4424.94 5471.37,4405.06 v1(5471.37,4346.09) 5471.37,4009.94 5539.37,3941.94 6113.37,3941.94 6209.37,3845.94 6209.37,3676.47 6254.91,3630.94 6401.52,3630.94 6430.8,3601.66 J1.16@6430.8,3559.94 ; v1@6330.37,5391.94 J5.6@6330.37,5657.94
  Bottom Layer w6: v1(5471.37,4346.09) 5207.22,4346.09 5123.37,4429.94 5123.37,5322.94 5190.56,5390.13 6328.14,5390.13 v1(6329.95,5391.94)
D6: J1.5 J5.7 U3.29 | length 3897
  Top Layer w6: U3.29@5373.14,4695.59 v1(5302.37,4695.59) 5232.52,4695.59 5166.37,4629.44 5166.37,4059.75 5196.37,4029.75 5196.37,3745.06 5313.49,3627.94 5835.83,3627.94 5879.37,3584.39 5879.37,3510.51 J1.5@5930.37,3459.51 ; v1(6230.37,5123.94) J5.7@6230.37,5657.94
  Bottom Layer w6: v1(5302.37,4695.59) 5302.37,5089.94 5326.37,5113.94 6220.37,5113.94 v1(6230.37,5123.94)
D7: J2.21 J5.8 U3.21 | length 2563
  Top Layer w6: v1(5480.37,5141.94) 5480.37,5125.82 5491.25,5114.94 U3.21@5491.25,4833.38 ; J2.21@5830.37,5957.66 5900.65,6027.94 6347.37,6027.94 6380.37,5994.94 6380.37,5804.94 6306.37,5730.94 6203.37,5730.94 J5.8@6130.37,5657.94 6129.37,5656.94 6129.95,5656.36 6129.95,5160.36 v1(6130.37,5159.94)
  Bottom Layer w6: v1(5480.37,5141.94) 6112.37,5141.94 v1(6130.37,5159.94)
D8: J1.6 J3.1 J8.2 R10.2 U3.30 | length 5634.9
  Top Layer w6: U3.30@5373.14,4675.9 5332.34,4675.9 5326.37,4669.94 5282.34,4669.94 5276.37,4675.9 5252.34,4675.9 v1(5211.37,4634.94) 5183.37,4606.94 5183.37,4067.94 5222.37,4028.94 v1(5222.37,3941.94) 5222.37,3736.03 5318.46,3639.94 5850.8,3639.94 J1.6@5930.8,3559.94 ; J3.1@5970.37,5657.94 5970.37,5386.75 v1(6021.18,5335.94) ; v1@6634.37,5358.94 6691.52,5416.09 J8.2@6918.97,5416.09
  Bottom Layer w6: R10.2@4407.11,3721.58 4407.11,3755.67 4612.37,3960.94 5203.37,3960.94 v1(5222.37,3941.94) ; v1(5211.37,4634.94) 5175.37,4670.94 5175.37,5267.94 5243.37,5335.94 v1(6021.18,5335.94) 6025.99,5331.13 6607.56,5331.13 v1(6635.37,5358.94)
D9: J1.19 J3.2 U3.43 | length 4389.6
  Top Layer w6: U3.43@5550.31,4498.74 5550.31,4336.87 v1(5545.37,4331.94) 5545.37,4238.56 5557.99,4225.94 5557.99,4195.96 5557.56,4195.53 5557.56,4034.75 5600.37,3991.94 6157.37,3991.94 6253.37,3895.94 6253.37,3704.94 6284.37,3673.94 6511.37,3673.94 6582.37,3602.94 6582.37,3508.36 J1.19@6630.8,3459.94 ; v1(5848.37,5410.94) 5870.37,5432.94 J3.2@5870.37,5657.94
  Bottom Layer w6: v1(5545.37,4331.94) 5498.37,4331.94 5490.37,4323.94 5187.56,4323.94 5106.18,4405.32 5106.18,5333.72 5183.4,5410.94 5696.37,5410.94 ; v1@5546.37,4330.94 v1@5549.37,4333.94 ; 5696.37,5411.94 5697.37,5410.94 v1(5848.37,5410.94)
D10: J3.3 R35.1 R36.1 | length 2257.4
  Top Layer w6: R35.1@4960.86,4229.09 R35.1@4961.91,4228.04 ; R36.1@4963.91,4158.04 4961.91,4160.04 R35.1@4961.91,4228.04 ; v1(5056.18,4357.75) 5053.99,4359.94 4980.37,4359.94 4961.91,4341.47 R35.1@4961.91,4228.04 ; J3.3@5770.37,5657.94 5770.37,5494.94 v1(5771.37,5493.94)
  Bottom Layer w6: v1(5056.18,4357.75) 5056.18,5413.75 5136.37,5493.94 v1(5771.37,5493.94)
D11: J2.17 J3.4 U3.17 | length 1400.5
  Top Layer w6: U3.17@5569.99,4833.38 5569.99,5122.56 5670.37,5222.94 J3.4@5670.37,5657.94 5745.37,5732.94 5892.37,5732.94 5979.37,5819.94 5979.37,5906.66 J2.17@6029.95,5957.24
D12: J2.16 J3.5 R32.2 U3.16 | length 4355.5
  Top Layer w6: U3.16@5589.68,4833.38 5589.68,5116.24 5697.37,5223.94 v1(5697.37,5545.94)
  Bottom Layer w6: J2.16@6129.95,5857.24 6129.95,5837.52 6050.37,5757.94 5597.37,5757.94 5570.37,5730.94 J3.5@5570.37,5657.94 5570.37,5571.94 5596.37,5545.94 v1(5697.37,5545.94) 5792.37,5545.94 5849.37,5488.94 6670.37,5488.94 6743.37,5415.94 6743.37,4082.94 6694.37,4033.94 6636.37,4033.94 6594.95,3992.52 R32.2@6594.95,3933.13
D13: J2.15 J3.6 U3.15 | length 1948.4
  Top Layer w6: U3.15@5609.36,4833.38 5609.36,5107.93 5732.37,5230.94 5732.37,5519.94 v1(5731.37,5520.94)
  Bottom Layer w6: v1(5731.37,5520.94) 5730.37,5521.94 5557.37,5521.94 5470.37,5608.94 J3.6@5470.37,5657.94 5470.37,5709.94 5535.37,5774.94 6031.37,5774.94 6077.37,5820.94 6077.37,5904.66 J2.15@6129.95,5957.24
GND: B1.2 C1.2 C2.2 C3.2 C4.2 C8.1 C9.1 C10.1 C11.1 C12.1 C14.2 C15.2 C16.2 C17.2 C18.2 C19.2 C22.2 CB1.2 CB2.2 CB3.2 CB4.2 CB8.2 CB9.2 CB10.2 CB11.2 CN2.9 CN3.4 CN3.6 CN3.8 CN3.10 CN3.12 CN3.14 CN3.16 CN3.18 CN3.20 CN4.2 CN4.3 CN6.5 CN6.6 CN6.7 CN6.8 CN6.9 CN7.9 CT1.2 CT2.2 CT3.2 D4.1 J1.23 J2.23 J3.7 J4.6 J4.7 J7.6 J8.4 JP1.3 LED1.2 P1.5 R23.1 R39.1 R49.1 R51.1 T1.1 T2.1 TP1.2 TP3.4 U1.1 U2.2 U3.8 U3.23 U3.47 U5.2 U6.8 U6.20 U6.23 U6.35 U6.39 U6.40 U6.47 U7.2 | length 1506.8
  Top Layer w8: U3.8@5707.79,4695.59 5836.57,4695.59 v4(5837.37,4696.39)
  Top Layer w10: U6.23@3171.7,4609.24 3211.84,4609.24 3240.54,4637.94 ; U6.20@3171.7,4668.3 3220.37,4668.3 3235.37,4653.3 ; 3235.37,4652.94 3235.37,4653.3 ; v1(3294.92,4930.86) 3309.49,4916.29 U6.8@3309.49,4865.15 ; U6.35@3427.6,4530.5 3427.6,4613.3 v1(3422.04,4618.86) 3402.96,4637.94 3240.54,4637.94 ; U6.39@3506.34,4628.93 v1@3633.14,4628.93 ; U6.40@3506.34,4648.61 3613.45,4648.61 v1@3633.14,4628.93 ; U6.47@3506.34,4786.41 3543.84,4786.41 3555.37,4797.94 3555.37,4818.94 3533.37,4840.94 v1(3528.37,4840.94) ; v1(3639.13,4622.94) v1@3633.14,4628.93 ; U3.23@5451.88,4833.38 5451.88,4791.43 5470.37,4772.94 5520.37,4772.94 5535.37,4757.94 5535.37,4728.94 v1(5550.37,4713.94) ; v1(5574.37,4631.94) 5629.05,4577.26 U3.47@5629.05,4498.74 ; 3235.37,4653.3 3240.54,4648.13 3240.54,4637.94
  Bottom Layer w20: v4(5837.37,4696.39) 5861.52,4672.24 5881.6,4672.24 CB8.2@5957.46,4672.24
  other v1: 3060.37,3242.42 4587.37,3256.09 4061.26,3279.35 5190.37,3296.09 5467.37,3296.09 6167.37,3296.09 6667.37,3296.09 5850.37,3297.94 3060.52,3403.14 3398.13,3432.81 4061.26,3445.9 4379.19,3446.74 5128.5,3446.68 5311.37,3447.94 3217.13,3456.8 3683.22,3503.32 3261.35,3508.74 3461.89,3513.41 3060.52,3521.35 5211.37,3536.94 3613.8,3544.58 5530.37,3589.28 4067.37,3596.09 3920.91,3597.39 3684.69,3599.56 3395.91,3607.61 4637.37,3616.09 3062.03,3645.63 3471.34,3692.12 3684.53,3707.67 3812.17,3821.99 3883.51,3823.82 4781.1,3835.3 4969.42,3835.15 3110.93,3842.28 3812.17,3886.09 7101.37,3886.09 3141.21,3910.55 6430.37,3915.95 3879.61,3941.94 3469.38,3976.18 3248.13,4000.15 3931.6,4001.39 3470.64,4029.92 3687.16,4040.94 7113.13,4076.63 6403.67,4090.51 5690.37,4114.94 3870.94,4139.15 4711.37,4183.13 3871.37,4229.94 6472.37,4229.94 6603.37,4229.94 6264.37,4230.94 3513.13,4251.76 5354.37,4251.94 7106.9,4269.94 4911.37,4273.64 6895.66,4274.94 5955.37,4277.94 6251.37,4287.94 6440.07,4290.6 6547.37,4290.97 6129.37,4291.94 4856.37,4298.94 5723.43,4306.24 5849.73,4306.24 6634.37,4310.94 4547.37,4346.09 3464.13,4356.94 6130.37,4360.94 6440.37,4360.94 5787.94,4384.12 6895.66,4412.35 6440.37,4421.94 6549.37,4422.71 6644.39,4423.33 7103.37,4422.71 3184.92,4434.94 6129.37,4435.94 5331.27,4438.94 5848.37,4476.94 5371.37,4483.14 6307.71,4499.94 6200.37,4503.94 6435.57,4507.81 6594.98,4508.67 5331.27,4519.22 4856.37,4526.94 4968.37,4527.26 4607.37,4546.09 4411.01,4553.09 3639.13,4568.94 6436.37,4568.94 5505.37,4575.94 6129.37,4581.94 4727.37,4586.09 6593.37,4622.94 5456.37,4630.94 4357.37,4646.09 6113.79,4646.65 4497.37,4676.09 6434.37,4677.94 4855.37,4697.94 4966.37,4697.94 5631.37,4713.94 4757.84,4730.29 6126.57,4755.52 6593.56,4755.64 6286.37,4759.94 6149.01,4811.06 6427.37,4813.94 6046.37,4820.94 5725.29,4837.17 5854.6,4838.94 6378.57,4867.94 6175.46,4868.94 6279.37,4868.94 5386.37,4870.94 6066.37,4911.94 5851.83,4912.79 5724.37,4913.94 3406.07,4921.86 4959.37,4924.94 4857.37,4926.94 6593.56,4926.94 7103.37,4931.94 4592.77,4946.12 4714.37,4946.94 6491.62,4968.94 3442.07,4973.86 6383.81,4976.94 6594.37,4983.94 6104.94,5007.94 6210.75,5009.21 5343.37,5035.94 3119.32,5048.94 6332.5,5048.94 6007.37,5060.94 6210.5,5064.94 3357.55,5076.86 6331.77,5127.19 6517.12,5127.19 6430.37,5127.94 3118.79,5134.79 7104.37,5204.94 3119.32,5227.94 3412.37,5255.94 3381.07,5380.55 4865.22,5460.97 4931.57,5461.92 4993.67,5461.92 3672.55,5478.98 4419.37,5533.94 4522.37,5533.94 4317.37,5534.94 6630.37,5536.09 3292.92,5554.15 5921.07,5557.94 7105.37,5592.94 3416.1,5614.15 3672.55,5651.15 3906.37,5688.23 5346.86,5768.31 5078.37,5768.94 3906.37,5778.24 3906.37,5868.77 7103.08,5872.16 3044.21,5900.64 3674.02,5900.64 5533.37,5980.94 5330.24,5983.1 4974.85,5983.94 5138.37,5984.94 3107.07,6000.86 3642.07,6012.86 4567.37,6096.09 3067.48,6112.4 3661.48,6116.08 4032.08,6144.27 5103.32,6166.09 5567.37,6166.09 6037.37,6166.09 6717.37,6166.09
LD1: LD1.2 U6.10 | length 723.1
  Top Layer w6: U6.10@3270.12,4865.15 3270.12,5226.56 3333.71,5290.15 3555.55,5290.15 3567.55,5278.15 LD1.2@3567.55,5245.15
LD2: LD2.2 U6.11 | length 914.2
  Top Layer w6: U6.11@3250.44,4865.15 3250.44,5223.84 3328.74,5302.15 3593.55,5302.15 3614.55,5281.15 3614.55,5181.15 3604.45,5171.05 LD2.2@3568.51,5171.05
LD3: LD3.2 U6.12 | length 1043.7
  Top Layer w6: U6.12@3230.75,4865.15 3230.75,5221.13 3323.77,5314.15 3598.52,5314.15 3626.55,5286.12 3626.55,5108.15 3612.55,5094.15 LD3.2@3568.55,5094.15
LD4: LD4.2 U6.19 | length 1818.6
  Top Layer w6: v1(3128.55,4916.29) 3196.69,4916.29 3218.75,4938.35 3218.75,5226.1 3318.8,5326.15 3603.49,5326.15 3638.55,5291.09 3638.55,5034.15 3622.55,5018.15 LD4.2@3568.51,5018.15 ; v1(3148.58,4517.94) 3130.37,4536.14 3130.37,4682.09 3136.26,4687.98 U6.19@3171.7,4687.98
  Bottom Layer w6: v1(3128.55,4916.29) 3128.55,4537.97 v1(3148.58,4517.94)
M-ATLK_RX: R48.2 U6.31 | length 483.9
  Top Layer w6: U6.31@3348.86,4530.5 3348.86,4464.46 3316.55,4432.15 3316.55,4362.81 3507.55,4171.81 R48.2@3507.55,4139.15
M-ATLK_TX: R47.2 U6.30 | length 457.3
  Top Layer w6: U6.30@3329.18,4530.5 3329.18,4468.78 3301.81,4441.41 3301.81,4304.89 3433.55,4173.15 R47.2@3433.55,4139.15
M-BOOT0: J9.2 U6.44 | length 154.6
  Top Layer w6: U6.44@3506.34,4727.35 3577.75,4727.35 J9.2@3636.55,4786.15
M-NRST: C22.1 P1.4 U6.7 | length 1411.3
  Top Layer w6: v1(3326.07,4949.86) 3326.07,4899.14 3329.18,4896.03 U6.7@3329.18,4865.15 3329.18,4808.58 v1(3328.74,4808.15)
  Bottom Layer w6: v1(3326.07,4949.86) 3664.51,4949.86 3686.14,4928.23 3686.14,4197.74 P1.4@3605.55,4117.15 ; C22.1@3328.05,4753.48 v1@3328.05,4808.15
M-SWCLK: P1.3 U6.37 | length 520.5
  Top Layer w6: U6.37@3506.34,4589.56 3506.34,4388.05 3531.25,4363.15 3637.55,4363.15 3659.55,4341.15 3659.55,4271.15 P1.3@3605.55,4217.15
M-SWDIO: P1.2 U6.34 | length 391.9
  Top Layer w6: U6.34@3407.92,4530.5 3407.92,4349.78 3440.55,4317.15 P1.2@3605.55,4317.15
M-USB_DM: R38.2 U6.32 | length 1610.6
  Top Layer w6: v1(3358.55,4436.15) 3368.55,4446.15 U6.32@3368.55,4530.5 ; v1(3367.13,5460.15) 3367.13,5686.73 3389.55,5709.15 R38.2@3389.55,5748
  Bottom Layer w6: v1(3358.55,4436.15) 3297.34,4436.15 3175.55,4557.94 3175.55,5268.57 v1(3367.13,5460.15)
M-USB_DP: R37.2 U6.33 | length 1687.9
  Top Layer w6: R37.2@3315.55,5747.04 3315.55,5712.15 3334.13,5693.57 v1(3334.13,5460.15) ; v1(3358.55,4393.15) 3388.23,4422.83 U6.33@3388.23,4530.5
  Bottom Layer w6: v1(3334.13,5460.15) 3163.55,5289.57 3163.55,4545.14 3315.54,4393.15 v1(3358.55,4393.15)
NRST: B1.1 CB1.1 CN2.7 CN3.15 CN7.7 J2.7 J4.3 J7.5 R46.1 U3.7 | length 10225.7
  Top Layer w6: v1(3312.5,3626.09) v1(3312.55,3863.94) ; v1(3312.55,3863.94) 3312.55,3964.63 3362.55,4014.63 3362.55,4076.15 R46.1@3359.55,4079.15 ; CN2.7@4147.19,3821.2 4199.54,3768.85 v1(4562.37,3768.85) 4562.37,3690.13 CB1.1@4557.33,3685.09 4557.33,3540.94 B1.1@4562.37,3535.9 B1.1@4203.37,3535.9 ; v1(5379.37,3892.94) 5380.37,3892.94 5428.37,3844.94 5609.37,3844.94 5630.37,3823.94 J4.3@5630.37,3757.94 ; U3.7@5707.79,4675.9 5707.79,4673.61 5885.04,4673.61 5975.37,4763.94 5975.37,4876.94 6036.37,4937.94 6395.37,4937.94 6477.37,5019.94 v1(6477.37,5292.94) 6477.37,5687.09 6581.37,5791.09 6581.37,5905.81 J2.7@6529.95,5957.24 ; v1(5876.37,4114.94) v1(6780.37,4114.94) ; v1(6644.37,5265.94) 6761.37,5148.94 6761.37,4977.94 6801.37,4937.94 6981.52,4937.94 7012.37,4907.09 7012.37,4735.09 6985.37,4708.09 6894.95,4708.09 J7.5@6845.37,4658.51
  Bottom Layer w6: CN7.7@3262.55,3359.15 3262.55,3441.12 3312.55,3491.12 ; 3312.5,3491.17 v1(3312.5,3626.09) ; v1(3312.55,3863.94) 3533.97,3863.94 3623.21,3774.7 3929.98,3774.7 3975.37,3820.09 3975.37,4272.09 4080.37,4377.09 4080.37,4612.09 4061.37,4631.09 3950.37,4631.09 CN3.15@3899.37,4682.09 ; 3978.2,3821.2 CN2.7@4147.19,3821.2 ; v1(4562.37,3768.85) 4686.46,3892.94 v1(5379.37,3892.94) 5774.37,3892.94 5877.37,3995.94 v1@5877.37,4114.94 ; v1(6477.37,5292.94) 6617.37,5292.94 v1(6644.37,5265.94) ; v1(6780.37,4114.94) 6780.37,4593.51 J7.5@6845.37,4658.51
PA11: J1.8 U3.32 | length 1880.9
  Top Layer w6: U3.32@5373.14,4636.53 5277.97,4636.53 5215.37,4573.94 5215.37,4085.75 5266.18,4034.94 5266.18,3735.19 5337.43,3663.94 5926.8,3663.94 6030.37,3560.36 J1.8@6030.37,3559.51
PA12: J1.9 U3.33 | length 2013.3
  Top Layer w6: U3.33@5373.14,4616.85 5287.28,4616.85 5230.37,4559.94 5230.37,4099.94 5282.37,4047.94 5282.37,3742.94 5349.37,3675.94 5987.83,3675.94 6080.37,3583.39 6080.37,3510.36 J1.9@6130.8,3459.94
PA13: CN2.3 CN3.7 CN7.3 J1.10 R44.1 U3.34 | length 6489
  Top Layer w6: R44.1@3211.55,4081.15 3211.55,3975.89 v1(3237.09,3950.34) 3237.09,3632.89 3462.55,3407.43 CN7.3@3462.55,3359.15 ; v1(3684.69,3860.62) 3684.69,3798.26 3684.37,3797.94 3709.16,3773.15 3880.73,3773.15 3915.18,3807.6 3915.18,3939.9 3996.48,4021.2 CN2.3@4147.19,4021.2 ; U3.34@5373.14,4597.16 5298.6,4597.16 5247.37,4545.94 5247.37,4114.94 5304.37,4057.94 v1(5304.37,4006.94) 5304.37,3742.94 5357.37,3689.94 6000.8,3689.94 J1.10@6130.8,3559.94
  Bottom Layer w6: v1(3237.09,3950.34) 3594.97,3950.34 v1(3684.69,3860.62) ; CN3.7@3899.37,5082.09 3948.37,5033.09 4091.37,5033.09 4116.37,5008.09 4116.37,4333.94 4001.92,4219.49 4001.92,4073.39 4054.11,4021.2 CN2.3@4147.19,4021.2 4193.16,3975.22 4321.21,3975.22 4352.92,4006.94 5103.97,4006.94 5104.37,4007.34 5267.37,4007.34 5267.77,4006.94 v1(5304.37,4006.94)
PA14: CN2.5 CN3.9 CN7.5 J1.13 R41.1 U3.37 | length 6492.6
  Top Layer w6: R41.1@3137.55,4081.15 3137.55,3954.46 v1(3199.07,3892.94) 3199.07,3606.86 3362.55,3443.38 CN7.5@3362.55,3359.15 ; v1(3634.55,3803.94) 3690.15,3748.34 3889.86,3748.34 3939.18,3797.66 3939.18,3890.39 3969.99,3921.2 CN2.5@4147.19,3921.2 ; U3.37@5432.2,4498.74 5432.2,4426.97 5402.56,4397.34 v1(5402.56,3984.94) 5492.56,3894.94 5972.06,3894.94 v1(5996.37,3870.62)
  Bottom Layer w6: v1(3199.07,3892.94) 3545.55,3892.94 v1(3634.55,3803.94) ; CN3.9@3899.37,4982.09 3950.37,4931.09 4073.37,4931.09 4104.37,4900.09 4104.37,4361.82 3987.37,4244.82 3987.37,3945.2 4011.37,3921.2 CN2.5@4147.19,3921.2 4193.38,3875.01 4302.37,3875.01 4419.3,3991.94 4627.56,3991.94 5263.37,3991.94 5279.37,3991.94 5288.37,3982.94 5400.56,3982.94 v1(5402.56,3984.94) ; v1(5996.37,3870.62) 5998.06,3868.94 6147.37,3868.94 6212.37,3803.94 6212.37,3661.94 6274.8,3599.51 6274.8,3515.93 J1.13@6330.8,3459.94
PA15: J1.14 R36.2 U3.38 | length 2078.5
  Top Layer w6: R36.2@5026.84,4158.02 5026.92,4157.94 v1(5078.37,4157.94) ; U3.38@5451.88,4498.74 5451.88,4429.69 5423.37,4401.18 v1(5423.37,4158.94) 5423.37,4008.94 5519.37,3912.94 6014.52,3912.94 v1(6028.37,3899.09)
  Bottom Layer w6: v1(5078.37,4157.94) 5079.37,4158.94 v1(5423.37,4158.94) ; v1(6028.37,3899.09) 6139.37,3899.09 6224.37,3814.09 6224.37,3666.91 6330.8,3560.48 J1.14@6330.8,3559.94
PB1: J2.19 R34.2 U3.19 | length 4104.1
  Top Layer w6: U3.19@5530.62,4833.38 5530.62,5136.19 5620.37,5225.94 v1(5620.37,5588.94) 5620.37,5704.94 5665.37,5749.94 5833.37,5749.94 5880.37,5796.94 5880.37,5898.94 5929.95,5948.52 J2.19@5929.95,5957.24
  Bottom Layer w6: v1(5620.37,5588.94) 5807.37,5588.94 5886.37,5509.94 6674.52,5509.94 6756.37,5428.09 6756.37,4063.94 6830.43,3989.88 R34.2@6830.43,3944.92
PB2: J2.20 U3.20 | length 1503.7
  Top Layer w6: v1(5454.37,5561.94) 5511.37,5504.94 5511.37,5456.94 5510.94,5456.5 U3.20@5510.94,4833.38
  Bottom Layer w6: v1(5454.37,5561.94) 5418.37,5597.94 5418.37,5737.09 5470.22,5788.94 5861.65,5788.94 J2.20@5929.95,5857.24
PB6: J1.18 R35.2 U3.42 | length 2321.9
  Top Layer w6: R35.2@5024.84,4228.02 5077.29,4228.02 v1(5077.37,4227.94) ; U3.42@5530.62,4498.74 5530.62,4385.94 5516.37,4371.69 5516.37,4230.94 5535.37,4211.94 v1(5535.37,4210.94) 5535.37,4016.94 5578.37,3973.94 6134.52,3973.94 6238.37,3870.09 6238.37,3696.94 6275.46,3659.85 6469.46,3659.85 6530.8,3598.51 J1.18@6530.8,3559.94
  Bottom Layer w6: v1(5077.37,4227.94) 5094.37,4210.94 v1(5535.37,4210.94)
PB8: J1.21 J3.10 R33.2 U3.45 | length 4498.5
  Top Layer w6: J3.10@5070.37,5657.94 5070.37,5570.94 5109.37,5531.94 v1(5109.37,5406.94) ; U3.45@5589.68,4498.74 5589.68,4281.63 v1(5601.37,4269.94) 5601.37,4074.09 5652.52,4022.94 6196.37,4022.94 6254.37,3964.94 6615.37,3964.94 6680.37,3899.94 6680.37,3510.36 J1.21@6730.8,3459.94
  Bottom Layer w6: v1(5109.37,5406.94) 5072.18,5369.75 5072.18,4380.13 5160.37,4291.94 5579.37,4291.94 v1(5601.37,4269.94) ; J1.21@6730.8,3459.94 6781.8,3510.94 6867.22,3510.94 6889.37,3533.09 6889.37,3848.94 6867.39,3870.92 R33.2@6830.43,3870.92
PB9: J1.22 J3.9 R31.2 U3.46 | length 3927.6
  Top Layer w6: v1(5145.37,5408.94) 5170.37,5433.94 J3.9@5170.37,5657.94 ; U3.46@5609.36,4498.74 5609.36,4344.95 5624.37,4329.94 v1(5624.37,4307.94) 5624.37,4071.94 5657.93,4038.38 6213.93,4038.38 6254.37,3997.94 v1(6658.74,3997.94)
  Bottom Layer w6: v1(5145.37,5408.94) 5088.18,5351.75 5088.18,4397.13 5177.37,4307.94 5592.75,4307.94 ; v1@5623.67,4306.94 5622.86,4307.75 5592.75,4307.94 ; v1(5624.37,4307.94) 5592.75,4307.94 ; v1(6658.74,3997.94) 6658.74,3973.57 6668.65,3963.66 R31.2@6668.65,3933.56 6702.98,3933.56 6717.37,3919.16 6717.37,3855.94 6781.37,3791.94 6781.37,3666.49 6781.92,3665.94 6730.8,3614.82 J1.22@6730.8,3559.94
PB11: J2.22 J7.8 LED4.2 U3.22 | length 4038.2
  Top Layer w6: LED4.2@4968.57,5282.5 5340.81,5282.5 5374.37,5248.94 v1(5374.37,5182.09) 5374.37,5062.13 5471.57,4964.94 U3.22@5471.57,4833.38 ; v1(5537.37,5182.94) 5536.37,5183.94 5536.37,5581.09 5521.37,5596.09 5521.37,5719.94 5569.37,5767.94 5790.37,5767.94 5829.95,5807.52 J2.22@5829.95,5857.24 ; v1(6663.37,5081.94) 6701.37,5043.94 6701.37,4515.09 6724.37,4492.09 6929.37,4492.09 6945.37,4508.09 J7.8@6945.37,4558.51
  Bottom Layer w6: v1(5374.37,5182.09) 5374.52,5181.94 5536.37,5181.94 v1(5537.37,5182.94) 6562.37,5182.94 v1(6663.37,5081.94)
PB12: J1.1 J7.7 U3.25 | length 4532.3
  Top Layer w6: U3.25@5373.14,4774.33 5296.98,4774.33 v1(5275.37,4795.94) 5205.37,4795.94 5112.37,4702.94 5112.37,4018.94 5146.37,3984.94 5146.37,3690.94 5377.37,3459.94 J1.1@5730.8,3459.94 ; v1(6664.37,5115.94) 6713.37,5066.94 6713.37,4585.09 6739.95,4558.51 J7.7@6845.37,4558.51
  Bottom Layer w6: v1(5275.37,4795.94) 5275.37,5175.94 5311.37,5211.94 6568.37,5211.94 v1(6664.37,5115.94)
